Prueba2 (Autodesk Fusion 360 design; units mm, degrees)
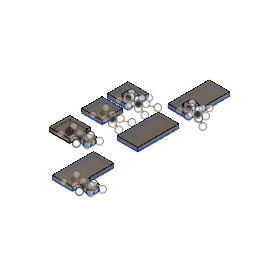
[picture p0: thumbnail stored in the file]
sketch "Sketch1"
  dimension "d1" = 80
  dimension "d2" = 80
  dimension "d24" = 30
  dimension "d25" = 30
  dimension "d26" = 50
  dimension "d27" = 100
  dimension "d28" = 12
  dimension "d29" = 80
  dimension "d30" = 80
  dimension "d31" = 30
  dimension "d32" = 30
  dimension "d33" = 50
  dimension "d34" = 100
  dimension "d38" = 30
  dimension "d39" = 30
  dimension "d40" = 50
  dimension "d41" = 100
  dimension "d44" = 80
  dimension "d45" = 80
  dimension "d46" = 30
  dimension "d47" = 30
  dimension "d48" = 50
  dimension "d49" = 100
  dimension "d50" = 12
  dimension "d51" = 80
  dimension "d57" = 30
  dimension "d58" = 30
  dimension "d59" = 50
  dimension "d60" = 100
  dimension "d61" = 80
  dimension "d62" = 80
  dimension "d63" = 80
  dimension "d64" = 160
  dimension "d65" = 160
extrude "Extrude7" new body sketch "Sketch1" blind 15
